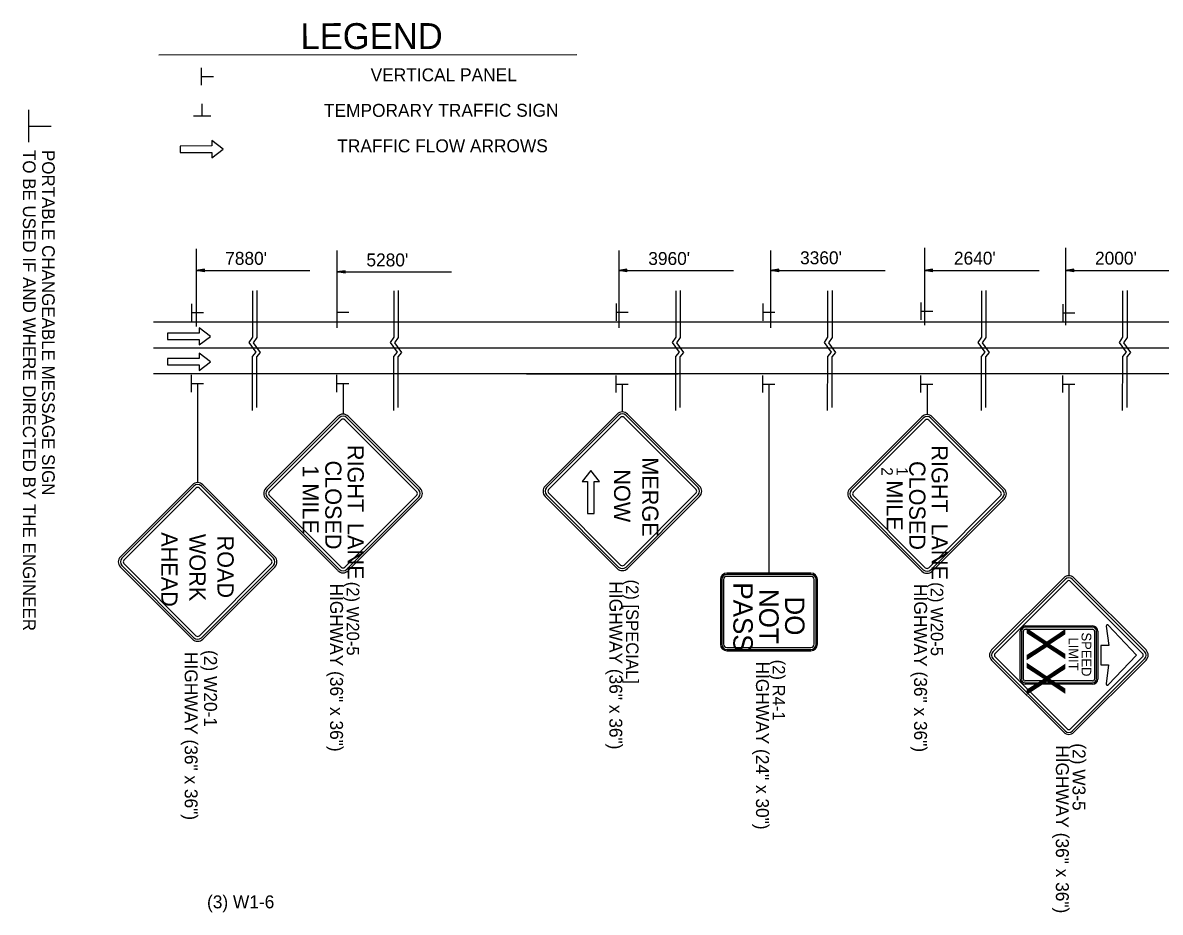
# Model space of a CAD drawing. Extents: x 1930579 to 1937521, y 596183 to 597599.
# Drawn here: x 1935128 to 1935656, y 596889 to 597301 of the extents above; entities that cross this region are included whole.
import ezdxf

# ---------------------------------------------------------------- set-up
doc = ezdxf.new("R2010")
doc.units = 0
for name, color, linetype in [('Default', 7, 'Continuous'), ('P_TC_Signs_Permanent', 7, 'Continuous'), ('P_TC_Signs_Temporary', 7, 'Continuous'), ('R_Annotation', 7, 'Continuous'), ('R_MOT', 7, 'Continuous'), ('R_Striping', 7, 'Continuous')]:
    doc.layers.add(name, color=color, linetype=linetype)

msp = doc.modelspace()

# ---------------------------------------------------------------- linework, layer by layer
at = {"layer": 'Default'}
for p, q in [((1935210.78, 597272.43), (1935210.78, 597280.41)), ((1935210.9, 597276.4), (1935216.35, 597276.4)), ((1935130.71, 597245.94), (1935130.71, 597260.96)), ((1935130.93, 597253.41), (1935141.18, 597253.41)), ((1935208.44, 597196.5), (1935208.44, 597160.58)), ((1935546.1, 597197.04), (1935546.1, 597161.13)), ((1935611.55, 597197.04), (1935611.55, 597161.13)), ((1935273.63, 597195.82), (1935273.63, 597159.91)), ((1935404.36, 597195.82), (1935404.36, 597159.91)), ((1935474.74, 597195.82), (1935474.74, 597159.91)), ((1935212.26, 597187.09), (1935208.44, 597186.51)), ((1935208.44, 597186.51), (1935261.07, 597186.51)), ((1935212.26, 597185.94), (1935208.44, 597186.51)), ((1935212.26, 597186.99), (1935209.08, 597186.51)), ((1935212.26, 597186.03), (1935209.08, 597186.51)), ((1935212.26, 597186.89), (1935209.73, 597186.51)), ((1935212.26, 597186.13), (1935209.73, 597186.51)), ((1935212.26, 597186.8), (1935210.37, 597186.51)), ((1935212.26, 597186.23), (1935210.37, 597186.51)), ((1935212.26, 597186.7), (1935211.02, 597186.51)), ((1935212.26, 597186.33), (1935211.02, 597186.51)), ((1935212.26, 597186.6), (1935211.66, 597186.51)), ((1935212.26, 597186.42), (1935211.66, 597186.51)), ((1935212.26, 597185.94), (1935212.26, 597187.09)), ((1935277.46, 597186.41), (1935273.63, 597185.83)), ((1935273.63, 597185.83), (1935326.86, 597185.83)), ((1935277.46, 597185.26), (1935273.63, 597185.83)), ((1935277.46, 597186.31), (1935274.27, 597185.83)), ((1935277.46, 597185.35), (1935274.27, 597185.83)), ((1935277.46, 597186.21), (1935274.93, 597185.83)), ((1935277.46, 597185.45), (1935274.93, 597185.83)), ((1935277.46, 597186.12), (1935275.57, 597185.83)), ((1935277.46, 597185.55), (1935275.57, 597185.83)), ((1935277.46, 597186.02), (1935276.21, 597185.83)), ((1935277.46, 597185.65), (1935276.21, 597185.83)), ((1935277.46, 597185.92), (1935276.85, 597185.83)), ((1935277.46, 597185.74), (1935276.85, 597185.83)), ((1935277.46, 597185.26), (1935277.46, 597186.41)), ((1935408.18, 597187.09), (1935404.36, 597186.51)), ((1935404.36, 597186.51), (1935457.59, 597186.51)), ((1935408.18, 597185.94), (1935404.36, 597186.51)), ((1935408.18, 597186.99), (1935405, 597186.51)), ((1935408.18, 597186.03), (1935405, 597186.51)), ((1935408.18, 597186.89), (1935405.65, 597186.51)), ((1935408.18, 597186.13), (1935405.65, 597186.51)), ((1935408.18, 597186.8), (1935406.29, 597186.51)), ((1935408.18, 597186.23), (1935406.29, 597186.51)), ((1935408.18, 597186.7), (1935406.94, 597186.51)), ((1935408.18, 597186.33), (1935406.94, 597186.51)), ((1935408.18, 597186.6), (1935407.58, 597186.51)), ((1935408.18, 597186.42), (1935407.58, 597186.51)), ((1935408.18, 597185.94), (1935408.18, 597187.09)), ((1935478.57, 597187.09), (1935474.74, 597186.51)), ((1935474.74, 597186.51), (1935527.97, 597186.51)), ((1935478.57, 597185.94), (1935474.74, 597186.51)), ((1935478.57, 597186.99), (1935475.38, 597186.51)), ((1935478.57, 597186.03), (1935475.38, 597186.51)), ((1935478.57, 597186.89), (1935476.04, 597186.51)), ((1935478.57, 597186.13), (1935476.04, 597186.51)), ((1935478.57, 597186.8), (1935476.67, 597186.51)), ((1935478.57, 597186.23), (1935476.67, 597186.51)), ((1935478.57, 597186.7), (1935477.32, 597186.51)), ((1935478.57, 597186.33), (1935477.32, 597186.51)), ((1935478.57, 597186.6), (1935477.96, 597186.51)), ((1935478.57, 597186.42), (1935477.96, 597186.51)), ((1935478.57, 597185.94), (1935478.57, 597187.09)), ((1935549.93, 597187.09), (1935546.1, 597186.51)), ((1935546.1, 597186.51), (1935599.33, 597186.51)), ((1935549.93, 597185.94), (1935546.1, 597186.51)), ((1935549.93, 597186.99), (1935546.74, 597186.51)), ((1935549.93, 597186.03), (1935546.74, 597186.51)), ((1935549.93, 597186.89), (1935547.4, 597186.51)), ((1935549.93, 597186.13), (1935547.4, 597186.51)), ((1935549.93, 597186.8), (1935548.04, 597186.51)), ((1935549.93, 597186.23), (1935548.04, 597186.51)), ((1935549.93, 597186.7), (1935548.69, 597186.51)), ((1935549.93, 597186.33), (1935548.69, 597186.51)), ((1935549.93, 597186.6), (1935549.32, 597186.51)), ((1935549.93, 597186.42), (1935549.32, 597186.51)), ((1935549.93, 597185.94), (1935549.93, 597187.09)), ((1935615.37, 597187.09), (1935611.55, 597186.51)), ((1935611.55, 597186.51), (1935664.78, 597186.51)), ((1935615.37, 597185.94), (1935611.55, 597186.51)), ((1935615.37, 597186.99), (1935612.18, 597186.51)), ((1935615.37, 597186.03), (1935612.18, 597186.51)), ((1935615.37, 597186.89), (1935612.84, 597186.51)), ((1935615.37, 597186.13), (1935612.84, 597186.51)), ((1935615.37, 597186.8), (1935613.48, 597186.51)), ((1935615.37, 597186.23), (1935613.48, 597186.51)), ((1935615.37, 597186.7), (1935614.13, 597186.51)), ((1935615.37, 597186.33), (1935614.13, 597186.51)), ((1935615.37, 597186.6), (1935614.77, 597186.51)), ((1935615.37, 597186.42), (1935614.77, 597186.51)), ((1935615.37, 597185.94), (1935615.37, 597187.09)), ((1935206.22, 597170.98), (1935206.22, 597163)), ((1935273.63, 597171.15), (1935273.63, 597163.17)), ((1935403.18, 597171.2), (1935403.18, 597163.22)), ((1935471.18, 597171.13), (1935471.18, 597163.15)), ((1935544.49, 597171.65), (1935544.49, 597163.68)), ((1935610.26, 597170.87), (1935610.26, 597162.89)), ((1935206.34, 597167.01), (1935211.78, 597167.01)), ((1935273.75, 597167.18), (1935279.2, 597167.18)), ((1935403.3, 597167.23), (1935408.75, 597167.23)), ((1935471.3, 597167.16), (1935476.75, 597167.16)), ((1935544.6, 597167.69), (1935550.05, 597167.69)), ((1935610.37, 597166.9), (1935615.82, 597166.9)), ((1936503.04, 597162.55), (1935188.53, 597162.55)), ((1936503.04, 597150.55), (1935188.53, 597150.55)), ((1936503.04, 597138.55), (1935188.53, 597138.55)), ((1935361.56, 597138.55), (1935431.95, 597138.55)), ((1935206.22, 597130.11), (1935206.22, 597138.09)), ((1935206.34, 597134.07), (1935211.78, 597134.07)), ((1935273.65, 597130.11), (1935273.65, 597138.09)), ((1935273.77, 597134.07), (1935279.21, 597134.07)), ((1935403.18, 597129.89), (1935403.18, 597137.87)), ((1935403.3, 597133.86), (1935408.75, 597133.86)), ((1935471.17, 597129.89), (1935471.17, 597137.87)), ((1935471.29, 597133.86), (1935476.73, 597133.86)), ((1935544.5, 597129.89), (1935544.5, 597137.87)), ((1935544.61, 597133.86), (1935550.06, 597133.86)), ((1935610.26, 597129.89), (1935610.26, 597137.87)), ((1935610.38, 597133.86), (1935615.83, 597133.86))]:
    msp.add_line(p, q, dxfattribs=at)
for points in [[(1935234.46, 597177.07), (1935234.46, 597155.55), (1935232.8, 597153.08), (1935236.04, 597148.65), (1935234.33, 597146.6), (1935234.33, 597121.58)], [(1935236.51, 597177.27), (1935236.51, 597155.46), (1935234.85, 597152.99), (1935238.08, 597148.56), (1935236.38, 597146.52), (1935236.38, 597123.02)], [(1935300.04, 597177.07), (1935300.04, 597155.55), (1935298.38, 597153.08), (1935301.62, 597148.65), (1935299.91, 597146.6), (1935299.91, 597121.58)], [(1935302.08, 597177.27), (1935302.08, 597155.46), (1935300.42, 597152.99), (1935303.66, 597148.56), (1935301.96, 597146.52), (1935301.95, 597123.02)], [(1935430.77, 597177.07), (1935430.77, 597155.55), (1935429.1, 597153.08), (1935432.34, 597148.65), (1935430.64, 597146.6), (1935430.63, 597121.58)], [(1935432.81, 597177.27), (1935432.81, 597155.46), (1935431.15, 597152.99), (1935434.39, 597148.56), (1935432.68, 597146.52), (1935432.68, 597123.02)], [(1935501.24, 597177.07), (1935501.24, 597155.55), (1935499.58, 597153.08), (1935502.81, 597148.65), (1935501.11, 597146.6), (1935501.1, 597121.58)], [(1935503.28, 597177.27), (1935503.28, 597155.46), (1935501.62, 597152.99), (1935504.86, 597148.56), (1935503.15, 597146.52), (1935503.15, 597123.02)], [(1935572.6, 597177.07), (1935572.6, 597155.55), (1935570.94, 597153.08), (1935574.18, 597148.65), (1935572.47, 597146.6), (1935572.47, 597121.58)], [(1935574.64, 597177.27), (1935574.64, 597155.46), (1935572.98, 597152.99), (1935576.22, 597148.56), (1935574.52, 597146.52), (1935574.51, 597123.02)], [(1935638.04, 597177.07), (1935638.04, 597155.55), (1935636.38, 597153.08), (1935639.62, 597148.65), (1935637.92, 597146.6), (1935637.91, 597121.58)], [(1935640.09, 597177.27), (1935640.09, 597155.46), (1935638.43, 597152.99), (1935641.66, 597148.56), (1935639.96, 597146.52), (1935639.96, 597123.02)]]:
    msp.add_lwpolyline(points, dxfattribs=at)
at = {"layer": 'P_TC_Signs_Permanent'}
for p, q in [((1935493.51, 597046.19), (1935454.51, 597046.19)), ((1935493.51, 597045.59), (1935454.51, 597045.59)), ((1935493.51, 597044.69), (1935454.51, 597044.69)), ((1935610.72, 597043.97), (1935577.31, 597010.55)), ((1935648.9, 597010.55), (1935615.49, 597043.97)), ((1935451.51, 597043.19), (1935451.51, 597013.19)), ((1935452.11, 597043.19), (1935452.11, 597013.19)), ((1935453.01, 597043.19), (1935453.01, 597013.19)), ((1935495.01, 597013.19), (1935495.01, 597043.19)), ((1935495.91, 597013.19), (1935495.91, 597043.19)), ((1935496.51, 597013.19), (1935496.51, 597043.19)), ((1935611.38, 597043.3), (1935577.97, 597009.89)), ((1935612.31, 597042.37), (1935578.9, 597008.96)), ((1935647.31, 597008.96), (1935613.9, 597042.37)), ((1935648.24, 597009.89), (1935614.83, 597043.3)), ((1935590.51, 596997.07), (1935590.51, 597019.27)), ((1935592.91, 597021.67), (1935624.11, 597021.67)), ((1935626.51, 597019.27), (1935626.51, 596997.07)), ((1935454.51, 597011.69), (1935493.51, 597011.69)), ((1935454.51, 597010.79), (1935493.51, 597010.79)), ((1935454.51, 597010.19), (1935493.51, 597010.19)), ((1935577.97, 597006.44), (1935611.38, 596973.03)), ((1935578.9, 597007.37), (1935612.31, 596973.96)), ((1935613.9, 596973.96), (1935647.31, 597007.37)), ((1935614.83, 596973.03), (1935648.24, 597006.44)), ((1935577.31, 597005.78), (1935610.72, 596972.37)), ((1935615.49, 596972.37), (1935648.9, 597005.78)), ((1935624.11, 596994.67), (1935592.91, 596994.67))]:
    msp.add_line(p, q, dxfattribs=at)
for points in [[(1935591.11, 597019.27), (1935591.11, 596997.07)], [(1935592.01, 596997.07), (1935592.01, 597019.27)], [(1935624.11, 597021.07), (1935592.91, 597021.07)], [(1935592.91, 597020.17), (1935624.11, 597020.17)], [(1935625.01, 597019.27), (1935625.01, 597008.17), (1935625.01, 596997.07)], [(1935625.91, 596997.07), (1935625.91, 597008.17), (1935625.91, 597019.27)], [(1935630.46, 597021.63), (1935631.58, 597012.67), (1935628.01, 597012.67), (1935628.01, 597003.67), (1935631.57, 597003.67), (1935630.46, 596994.78)], [(1935631.42, 596994.32), (1935644.51, 597008.2), (1935631.42, 597022.08)], [(1935624.11, 596996.17), (1935592.91, 596996.17)], [(1935592.91, 596995.27), (1935624.11, 596995.27)]]:
    msp.add_lwpolyline(points, dxfattribs=at)
for centre, radius, start, end in [((1935454.51, 597043.19), 3, 90, 180), ((1935454.51, 597043.19), 2.4, 90, 180), ((1935454.51, 597043.19), 1.5, 90, 180), ((1935493.51, 597043.19), 3, 360, 90), ((1935493.51, 597043.19), 2.4, 360, 90), ((1935493.51, 597043.19), 1.5, 360, 90), ((1935613.1, 597041.58), 3.38, 45, 135), ((1935613.1, 597041.58), 2.44, 45, 135), ((1935613.1, 597041.58), 1.13, 45, 135), ((1935631.02, 597021.7), 0.563, 43.3117, 187.125), ((1935592.91, 597019.27), 2.4, 90, 180), ((1935592.91, 597019.27), 1.8, 90, 180), ((1935592.91, 597019.27), 0.9, 90, 180), ((1935624.11, 597019.27), 2.4, 0, 90), ((1935624.11, 597019.27), 1.8, 0, 90), ((1935624.11, 597019.27), 0.9, 0, 90), ((1935454.51, 597013.19), 3, 180, 270), ((1935454.51, 597013.19), 2.4, 180, 270), ((1935454.51, 597013.19), 1.5, 180, 270), ((1935493.51, 597013.19), 3, 270, 360), ((1935493.51, 597013.19), 2.4, 270, 360), ((1935493.51, 597013.19), 1.5, 270, 360), ((1935579.69, 597008.17), 3.38, 135, 225), ((1935579.69, 597008.17), 2.44, 135, 225), ((1935579.69, 597008.17), 1.13, 135, 225), ((1935646.51, 597008.17), 1.13, 315, 45), ((1935646.51, 597008.17), 2.44, 315, 45), ((1935646.51, 597008.17), 3.38, 315, 45), ((1935592.91, 596997.07), 2.4, 180, 270), ((1935592.91, 596997.07), 1.8, 180, 270), ((1935592.91, 596997.07), 0.9, 180, 270), ((1935624.11, 596997.07), 2.4, 270, 0), ((1935624.11, 596997.07), 1.8, 270, 0), ((1935624.11, 596997.07), 0.9, 270, 0), ((1935631.02, 596994.71), 0.563, 172.875, 316.6883), ((1935613.1, 596974.76), 3.38, 225, 315), ((1935613.1, 596974.76), 2.44, 225, 315), ((1935613.1, 596974.76), 1.13, 225, 315)]:
    msp.add_arc(centre, radius, start, end, dxfattribs=at)
at = {"layer": 'P_TC_Signs_Temporary'}
for p, q in [((1935240.69, 597085.51), (1935274.1, 597118.92)), ((1935241.36, 597084.85), (1935274.77, 597118.26)), ((1935242.29, 597083.92), (1935275.7, 597117.33)), ((1935277.29, 597117.33), (1935310.7, 597083.92)), ((1935278.21, 597118.26), (1935311.63, 597084.85)), ((1935278.88, 597118.92), (1935312.29, 597085.51)), ((1935370.23, 597086.53), (1935403.64, 597119.94)), ((1935370.89, 597085.87), (1935404.3, 597119.28)), ((1935371.82, 597084.94), (1935405.23, 597118.35)), ((1935406.82, 597118.35), (1935440.23, 597084.94)), ((1935407.75, 597119.28), (1935441.16, 597085.87)), ((1935408.41, 597119.94), (1935441.82, 597086.53)), ((1935511.54, 597085.29), (1935544.95, 597118.71)), ((1935512.2, 597084.63), (1935545.61, 597118.04)), ((1935549.06, 597118.04), (1935582.47, 597084.63)), ((1935549.72, 597118.71), (1935583.13, 597085.29)), ((1935513.13, 597083.7), (1935546.54, 597117.11)), ((1935548.13, 597117.11), (1935581.54, 597083.7)), ((1935173.26, 597053.77), (1935206.67, 597087.18)), ((1935173.93, 597053.11), (1935207.34, 597086.52)), ((1935174.85, 597052.18), (1935208.26, 597085.59)), ((1935209.86, 597085.59), (1935243.27, 597052.18)), ((1935210.78, 597086.52), (1935244.19, 597053.11)), ((1935211.45, 597087.18), (1935244.86, 597053.77)), ((1935274.1, 597047.33), (1935240.69, 597080.74)), ((1935274.77, 597047.99), (1935241.36, 597081.4)), ((1935275.7, 597048.92), (1935242.29, 597082.33)), ((1935310.7, 597082.33), (1935277.29, 597048.92)), ((1935311.63, 597081.4), (1935278.21, 597047.99)), ((1935312.29, 597080.74), (1935278.88, 597047.33)), ((1935403.64, 597048.35), (1935370.23, 597081.76)), ((1935404.3, 597049.01), (1935370.89, 597082.42)), ((1935405.23, 597049.94), (1935371.82, 597083.35)), ((1935440.23, 597083.35), (1935406.82, 597049.94)), ((1935441.16, 597082.42), (1935407.75, 597049.01)), ((1935441.82, 597081.76), (1935408.41, 597048.35)), ((1935544.95, 597047.11), (1935511.54, 597080.52)), ((1935545.61, 597047.77), (1935512.2, 597081.18)), ((1935546.54, 597048.7), (1935513.13, 597082.11)), ((1935581.54, 597082.11), (1935548.13, 597048.7)), ((1935582.47, 597081.18), (1935549.06, 597047.77)), ((1935583.13, 597080.52), (1935549.72, 597047.11)), ((1935206.67, 597015.58), (1935173.26, 597049)), ((1935207.34, 597016.25), (1935173.93, 597049.66)), ((1935208.26, 597017.18), (1935174.85, 597050.59)), ((1935243.27, 597050.59), (1935209.86, 597017.18)), ((1935244.19, 597049.66), (1935210.78, 597016.25)), ((1935244.86, 597049), (1935211.45, 597015.58))]:
    msp.add_line(p, q, dxfattribs=at)
for centre, radius, start, end in [((1935276.49, 597116.53), 3.37, 45, 135), ((1935276.49, 597116.53), 2.44, 45, 135), ((1935276.49, 597116.53), 1.12, 45, 135), ((1935406.02, 597117.56), 3.37, 45, 135), ((1935406.02, 597117.56), 2.44, 45, 135), ((1935406.02, 597117.56), 1.12, 45, 135), ((1935547.34, 597116.32), 3.37, 45, 135), ((1935547.34, 597116.32), 2.44, 45, 135), ((1935547.34, 597116.32), 1.12, 45, 135), ((1935209.06, 597084.79), 3.37, 45, 135), ((1935209.06, 597084.79), 2.44, 45, 135), ((1935209.06, 597084.79), 1.12, 45, 135), ((1935243.08, 597083.12), 3.37, 135, 225), ((1935309.9, 597083.12), 3.38, 315, 45), ((1935372.61, 597084.14), 3.37, 135, 225), ((1935372.61, 597084.14), 2.44, 135, 225), ((1935439.44, 597084.14), 2.44, 315, 45), ((1935439.44, 597084.14), 3.38, 315, 45), ((1935243.08, 597083.12), 2.44, 135, 225), ((1935243.08, 597083.12), 1.13, 135, 225), ((1935309.9, 597083.12), 1.13, 315, 45), ((1935309.9, 597083.12), 2.44, 315, 45), ((1935372.61, 597084.14), 1.13, 135, 225), ((1935439.44, 597084.14), 1.13, 315, 45), ((1935513.93, 597082.91), 3.37, 135, 225), ((1935513.93, 597082.91), 2.44, 135, 225), ((1935513.93, 597082.91), 1.13, 135, 225), ((1935580.75, 597082.91), 1.13, 315, 45), ((1935580.75, 597082.91), 2.44, 315, 45), ((1935580.75, 597082.91), 3.38, 315, 45), ((1935175.65, 597051.38), 3.37, 135, 225), ((1935175.65, 597051.38), 2.44, 135, 225), ((1935175.65, 597051.38), 1.13, 135, 225), ((1935242.47, 597051.38), 1.13, 315, 45), ((1935242.47, 597051.38), 2.44, 315, 45), ((1935242.47, 597051.38), 3.38, 315, 45), ((1935276.49, 597049.71), 1.12, 225, 315), ((1935406.02, 597050.73), 2.44, 225, 315), ((1935406.02, 597050.73), 1.12, 225, 315), ((1935547.34, 597049.5), 1.12, 225, 315), ((1935276.49, 597049.71), 3.38, 225, 315), ((1935276.49, 597049.71), 2.44, 225, 315), ((1935406.02, 597050.73), 3.38, 225, 315), ((1935547.34, 597049.5), 3.38, 225, 315), ((1935547.34, 597049.5), 2.44, 225, 315), ((1935209.06, 597017.97), 1.12, 225, 315), ((1935209.06, 597017.97), 3.38, 225, 315), ((1935209.06, 597017.97), 2.44, 225, 315)]:
    msp.add_arc(centre, radius, start, end, dxfattribs=at)
at = {"layer": 'R_Annotation'}
for p, q in [((1935191, 597286.46), (1935384.92, 597286.59)), ((1935211.16, 597258.26), (1935211.16, 597263.72)), ((1935215.14, 597258.14), (1935207.14, 597258.14)), ((1935209.06, 597134.08), (1935209.06, 597088.17)), ((1935209.06, 597134.07), (1935209.06, 597089.62)), ((1935276.49, 597134.07), (1935276.49, 597119.91)), ((1935406.02, 597133.86), (1935406.02, 597120.93)), ((1935474.01, 597133.86), (1935474.01, 597046.19)), ((1935547.34, 597133.86), (1935547.34, 597119.69)), ((1935613.1, 597133.86), (1935613.1, 597044.95))]:
    msp.add_line(p, q, dxfattribs=at)
at = {"layer": 'R_MOT'}
for points in [[(1935215.65, 597238.74), (1935220.84, 597242.75), (1935215.65, 597246.74), (1935215.65, 597244.24), (1935200.94, 597244.23), (1935200.94, 597241.23), (1935215.65, 597241.24)], [(1935395.41, 597088.6), (1935391.41, 597093.79), (1935387.41, 597088.6), (1935389.91, 597088.6), (1935389.91, 597073.89), (1935392.91, 597073.89), (1935392.91, 597088.6)]]:
    msp.add_lwpolyline(points, close=True, dxfattribs=at)
at = {"layer": 'R_Striping'}
for points in [[(1935209.8, 597151.97), (1935214.99, 597155.97), (1935209.8, 597159.97), (1935209.8, 597157.47), (1935195.09, 597157.47), (1935195.09, 597154.47), (1935209.8, 597154.47)], [(1935209.8, 597140.19), (1935214.99, 597144.19), (1935209.8, 597148.19), (1935209.8, 597145.69), (1935195.09, 597145.69), (1935195.09, 597142.69), (1935209.8, 597142.69)]]:
    msp.add_lwpolyline(points, close=True, dxfattribs=at)

# ---------------------------------------------------------------- texts
at = {"layer": 'Default'}
for s, height, rotation, p in [('TO BE USED IF AND WHERE DIRECTED BY THE ENGINEER', 5.8751, 270, (1935128.03, 597242.39)), ('PORTABLE CHANGEABLE MESSAGE SIGN', 5.8751, 270, (1935136.9, 597242.39)), ("7880'", 6, 360, (1935221.85, 597189.15)), ("5280'", 6, 360, (1935287.35, 597188.41)), ("3960'", 6, 360, (1935418.07, 597189.07)), ("3360'", 6, 360, (1935488.46, 597189.41)), ("2640'", 6, 360, (1935559.82, 597189.23)), ("2000'", 6, 360, (1935625.26, 597189.23))]:
    msp.add_text(s, height=height, rotation=rotation, dxfattribs=at).set_placement(p)
at = {"layer": 'P_TC_Signs_Permanent'}
for s, height, rotation, p in [('PASS', 9, 270, (1935457.51, 597041.9)), ('NOT', 9, 269.9596, (1935469.52, 597038.84)), ('DO', 9, 270, (1935481.51, 597035.36)), ('XX', 18, 270, (1935593.51, 597021.31)), ('SPEED', 4.5, 270, (1935619.01, 597018.67)), ('LIMIT', 4.5, 270, (1935613.01, 597016.36))]:
    msp.add_text(s, height=height, rotation=rotation, dxfattribs=at).set_placement(p)
at = {"layer": 'P_TC_Signs_Temporary'}
for s, height, p in [('RIGHT\u2002LANE', 7.5, (1935278.62, 597105.64)), ('RIGHT\u2002LANE', 7.5, (1935549.46, 597105.43)), ('CLOSED', 7.5, (1935268.24, 597098.38)), ('MERGE', 7.5, (1935415.24, 597099.9)), ('CLOSED', 7.5, (1935539.09, 597098.16)), ('1 MILE', 7.5, (1935257.74, 597096.17)), ('NOW', 7.5, (1935402.21, 597094.31)), ('2', 5.25, (1935526.21, 597095.26)), ('1', 5.25, (1935533.21, 597095.26)), (' MILE', 7.5, (1935528.59, 597092)), (' AHEAD ', 7.5, (1935192.23, 597067.92)), ('WORK', 7.5, (1935205.25, 597064.37)), (' ROAD ', 7.5, (1935218.27, 597066.4))]:
    msp.add_text(s, height=height, rotation=270, dxfattribs=at).set_placement(p)
at = {"layer": 'R_Annotation'}
for s, height, rotation, p in [('LEGEND', 12, 0.0388, (1935256.74, 597289.18)), ('VERTICAL PANEL', 6, 0.0388, (1935289.31, 597274.22)), ('TEMPORARY TRAFFIC SIGN', 6, 0.0388, (1935267.65, 597257.74)), ('TRAFFIC FLOW ARROWS', 6, 0.0388, (1935273.85, 597241.28)), ('HIGHWAY (36" x 36")', 6, 270, (1935270.49, 597041.34)), ('(2) W20-5', 5.76, 270, (1935278.21, 597042.2)), ('HIGHWAY (36" x 36")', 6, 270, (1935400.02, 597042.36)), ('(2) [SPECIAL]', 5.76, 270, (1935407.75, 597043.22)), ('HIGHWAY (36" x 36")', 6, 270, (1935541.34, 597041.12)), ('(2) W20-5', 5.76, 270, (1935549.06, 597041.99)), ('HIGHWAY (36" x 36")', 6, 270, (1935203.06, 597009.6)), ('(2) W20-1', 6, 270, (1935212.05, 597010.51)), ('HIGHWAY (24" x 30")', 6, 270, (1935468.01, 597005.19)), ('(2) R4-1', 5.76, 270, (1935475.72, 597006.06)), ('HIGHWAY (36" x 36")', 6, 270, (1935607.1, 596966.38)), ('(2) W3-5', 6, 270, (1935614.83, 596967.28)), ('(3) W1-6', 6, 0.0075, (1935213.41, 596890.75))]:
    msp.add_text(s, height=height, rotation=rotation, dxfattribs=at).set_placement(p)

doc.saveas('drawing.dxf')
